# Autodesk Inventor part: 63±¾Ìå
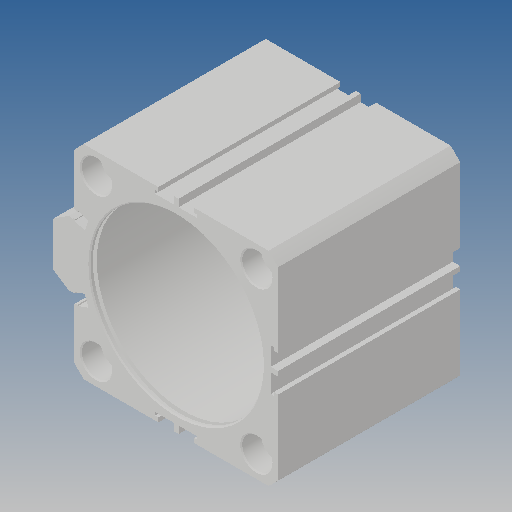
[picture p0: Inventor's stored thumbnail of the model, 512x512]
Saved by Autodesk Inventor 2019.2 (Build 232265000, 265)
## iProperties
Created: 2013-07
Part Number: 63±¾Ìå
Material: Ogólny
Document SubType Name: Modeling
Designer: CADENGINEERING4
Density: 1 g/cm^3
Appearance: Domyślna
Author: CADENGINEERING4
Revision Number: ÈÎºÎ
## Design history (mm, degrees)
feature "µ¹½Ç4"
node "Bryła1"
